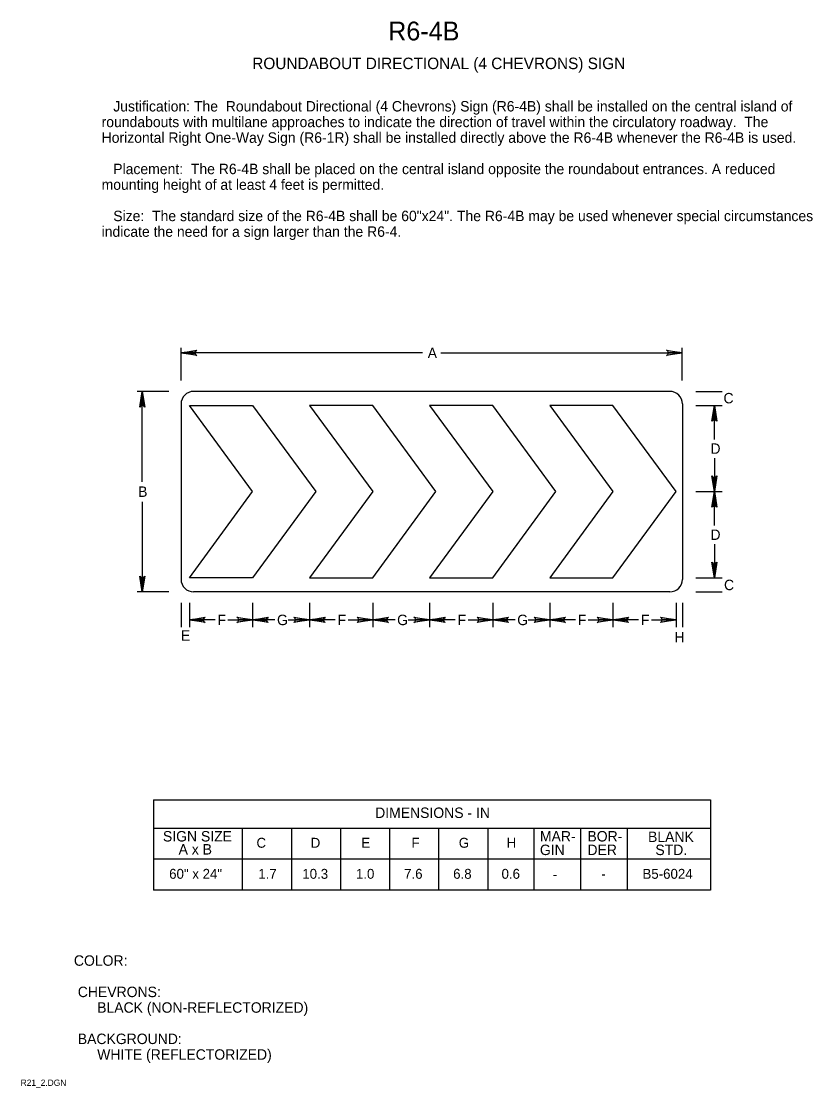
# Model space of a CAD drawing. Extents: x 0.013 to 0.202, y 0.004 to 0.259.
import ezdxf

# ---------------------------------------------------------------- set-up
doc = ezdxf.new("R2010")
doc.units = 0
for name, color, linetype in [('1', 7, 'Continuous'), ('2', 7, 'Continuous'), ('3', 7, 'Continuous')]:
    doc.layers.add(name, color=color, linetype=linetype)

# ---------------------------------------------------------------- blocks, each defined once
blk = doc.blocks.new('RARROW')
at = {"layer": '3'}
for p, q in [((-2.156, 0.285), (-2.2665, 0.384625)), ((-2.2665, 0.384625), (0, 0)), ((0, 0), (-2.2665, -0.379125)), ((-2.156, 0.285), (-2.075625, 0.12075)), ((0, 0), (-2.156, 0.285)), ((-2.14975, -0.2705), (0, 0)), ((-2.075625, 0.12075), (0, 0)), ((0, 0), (-2.074, -0.108)), ((-2.2665, -0.379125), (-2.14975, -0.2705)), ((-2.074, -0.108), (-2.14975, -0.2705))]:
    blk.add_line(p, q, dxfattribs=at)

msp = doc.modelspace()

# ---------------------------------------------------------------- linework, layer by layer
at = {"layer": '3'}
for p, q in [((0.05078, 0.1732), (0.05078, 0.18107)), ((0.10858, 0.17982), (0.05078, 0.17982)), ((0.11294, 0.17982), (0.17077, 0.17982)), ((0.17077, 0.1732), (0.17077, 0.18107)), ((0.04787, 0.17061), (0.04025, 0.17061)), ((0.0415, 0.14899), (0.0415, 0.17061)), ((0.16778, 0.17061), (0.05378, 0.17061)), ((0.17403, 0.17061), (0.18028, 0.17061)), ((0.05078, 0.16761), (0.05078, 0.12561)), ((0.0679, 0.14661), (0.05278, 0.16723)), ((0.05278, 0.16723), (0.0679, 0.16723)), ((0.17078, 0.16761), (0.17078, 0.12561)), ((0.17403, 0.16723), (0.18028, 0.16723)), ((0.17844, 0.15913), (0.17844, 0.16723)), ((0.17844, 0.15463), (0.17844, 0.14661)), ((0.05278, 0.12599), (0.0679, 0.14661)), ((0.17403, 0.14661), (0.18028, 0.14661)), ((0.17844, 0.1385), (0.17844, 0.14661)), ((0.0415, 0.1442), (0.0415, 0.12261)), ((0.17844, 0.13401), (0.17844, 0.12599)), ((0.17403, 0.12599), (0.18028, 0.12599)), ((0.04787, 0.12261), (0.04025, 0.12261)), ((0.16778, 0.12261), (0.05378, 0.12261)), ((0.17403, 0.12261), (0.18028, 0.12261)), ((0.05078, 0.12001), (0.05078, 0.11419)), ((0.05278, 0.12001), (0.05278, 0.11419)), ((0.0679, 0.12001), (0.0679, 0.11419)), ((0.08153, 0.12001), (0.08153, 0.11419)), ((0.09665, 0.12001), (0.09665, 0.11419)), ((0.11028, 0.12001), (0.11028, 0.11419)), ((0.1254, 0.12001), (0.1254, 0.11419)), ((0.13903, 0.12001), (0.13903, 0.11419)), ((0.15415, 0.12001), (0.15415, 0.11419)), ((0.16928, 0.12001), (0.16928, 0.11419)), ((0.17078, 0.12001), (0.17078, 0.11419)), ((0.05893, 0.11591), (0.0529, 0.11591)), ((0.062, 0.11591), (0.0679, 0.11591)), ((0.07325, 0.11591), (0.0679, 0.11591)), ((0.07641, 0.11591), (0.08153, 0.11591)), ((0.08768, 0.11591), (0.08165, 0.11591)), ((0.09075, 0.11591), (0.09665, 0.11591)), ((0.102, 0.11591), (0.09665, 0.11591)), ((0.10516, 0.11591), (0.11028, 0.11591)), ((0.11643, 0.11591), (0.1104, 0.11591)), ((0.1195, 0.11591), (0.1254, 0.11591)), ((0.13075, 0.11591), (0.1254, 0.11591)), ((0.13391, 0.11591), (0.13903, 0.11591)), ((0.14518, 0.11591), (0.13915, 0.11591)), ((0.14825, 0.11591), (0.15415, 0.11591)), ((0.1603, 0.11591), (0.15428, 0.11591)), ((0.16337, 0.11591), (0.16928, 0.11591)), ((0.04419, 0.07287), (0.17756, 0.07287)), ((0.04419, 0.07287), (0.04419, 0.05125)), ((0.17756, 0.07287), (0.17756, 0.05125)), ((0.17756, 0.066), (0.04419, 0.066)), ((0.06544, 0.066), (0.06544, 0.05125)), ((0.07719, 0.066), (0.07719, 0.05125)), ((0.08894, 0.066), (0.08894, 0.05125)), ((0.10069, 0.066), (0.10069, 0.05125)), ((0.11244, 0.066), (0.11244, 0.05125)), ((0.12419, 0.066), (0.12419, 0.05125)), ((0.12419, 0.066), (0.12419, 0.05262)), ((0.1352, 0.066), (0.1352, 0.05125)), ((0.14644, 0.066), (0.14644, 0.05125)), ((0.15756, 0.066), (0.15756, 0.05125)), ((0.17756, 0.05862), (0.04419, 0.05862)), ((0.17756, 0.05125), (0.04419, 0.05125))]:
    msp.add_line(p, q, dxfattribs=at)
msp.add_lwpolyline([(0.0679, 0.16723), (0.08302, 0.14661), (0.0679, 0.12599), (0.05278, 0.12599)], dxfattribs=at)
for points in [[(0.09665, 0.16723), (0.08153, 0.16723), (0.09665, 0.14661), (0.08153, 0.12599), (0.09665, 0.12599), (0.11177, 0.14661)], [(0.1254, 0.16723), (0.11028, 0.16723), (0.1254, 0.14661), (0.11028, 0.12599), (0.1254, 0.12599), (0.14052, 0.14661)], [(0.15415, 0.16723), (0.13903, 0.16723), (0.15415, 0.14661), (0.13903, 0.12599), (0.15415, 0.12599), (0.16927, 0.14661)]]:
    msp.add_lwpolyline(points, close=True, dxfattribs=at)
for centre, start, end in [((0.05378, 0.16761), 90, 180), ((0.16778, 0.16761), 0, 90), ((0.05378, 0.12561), 180, 270), ((0.16778, 0.12561), 270, 0)]:
    msp.add_arc(centre, 0.003, start, end, dxfattribs=at)

# ---------------------------------------------------------------- block references
at = {"layer": '3', "xscale": 0.0016545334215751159, "yscale": 0.0016366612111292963}
for p, rotation in [((0.05078, 0.17982), 180), ((0.0415, 0.17061), 90), ((0.17844, 0.16723), 90), ((0.17844, 0.14661), -90), ((0.17844, 0.14661), 90), ((0.17844, 0.12599), -90), ((0.0415, 0.12261), -90), ((0.05278, 0.11591), 180), ((0.0679, 0.11591), 180), ((0.08153, 0.11591), 180), ((0.09665, 0.11591), 180), ((0.11028, 0.11591), 180), ((0.1254, 0.11591), 180), ((0.13903, 0.11591), 180), ((0.15415, 0.11591), 180)]:
    msp.add_blockref('RARROW', p, dxfattribs=dict(at, rotation=rotation))
for p in [(0.17077, 0.17982), (0.0679, 0.11591), (0.08153, 0.11591), (0.09665, 0.11591), (0.11028, 0.11591), (0.1254, 0.11591), (0.13903, 0.11591), (0.15415, 0.11591), (0.16928, 0.11591)]:
    msp.add_blockref('RARROW', p, dxfattribs=at)

# ---------------------------------------------------------------- texts
at = {"layer": '1'}
for s, height, p in [('R6-4B', 0.0045, (0.10036, 0.25462)), ('ROUNDABOUT DIRECTIONAL (4 CHEVRONS) SIGN', 0.0027503, (0.06782, 0.24775)), ('COLOR:', 0.0025, (0.02513, 0.03312)), (' CHEVRONS:', 0.0025, (0.02513, 0.02562)), ('      BLACK (NON-REFLECTORIZED)', 0.0024998, (0.02513, 0.02188)), (' BACKGROUND:', 0.0024998, (0.02513, 0.01438)), ('      WHITE (REFLECTORIZED)', 0.0024998, (0.02513, 0.01063)), ('R21_2.DGN', 0.0015, (0.01238, 0.00438))]:
    msp.add_text(s, height=height, dxfattribs=at).set_placement(p)
at = {"layer": '2'}
for s, height, p in [('   Justification: The  Roundabout Directional (4 Chevrons) Sign (R6-4B) shall be installed on the central island of', 0.00249975, (0.03176, 0.23761)), ('roundabouts with multilane approaches to indicate the direction of travel within the circulatory roadway.  The ', 0.00249975, (0.03176, 0.23386)), ('Horizontal Right One-Way Sign (R6-1R) shall be installed directly above the R6-4B whenever the R6-4B is used.', 0.00249975, (0.03176, 0.23011)), ('   Placement:  The R6-4B shall be placed on the central island opposite the roundabout entrances. A reduced', 0.00249975, (0.03176, 0.22261)), ('mounting height of at least 4 feet is permitted.', 0.0024998, (0.03176, 0.21886)), ('   Size:  The standard size of the R6-4B shall be 60"x24". The R6-4B may be used whenever special circumstances ', 0.00249975, (0.03176, 0.21136)), ('indicate the need for a sign larger than the R6-4.', 0.0024998, (0.03176, 0.20761))]:
    msp.add_text(s, height=height, dxfattribs=at).set_placement(p)
at = {"layer": '3'}
for s, height, p in [('A', 0.0025, (0.10982, 0.17857)), ('C', 0.0025, (0.18063, 0.16774)), ('D', 0.0025, (0.17751, 0.15567)), ('B', 0.0025, (0.0405, 0.14536)), ('D', 0.0025, (0.17751, 0.13505)), ('C', 0.0025, (0.18076, 0.12303)), ('F', 0.0025, (0.05949, 0.11466)), ('G', 0.0025, (0.07375, 0.11466)), ('F', 0.0025, (0.08824, 0.11466)), ('G', 0.0025, (0.1025, 0.11466)), ('F', 0.0025, (0.11699, 0.11466)), ('G', 0.0025, (0.13125, 0.11466)), ('F', 0.0025, (0.14574, 0.11466)), ('F', 0.0025, (0.16086, 0.11466)), ('E', 0.0025, (0.05076, 0.11092)), ('H', 0.0025, (0.16889, 0.11054)), ('DIMENSIONS - IN', 0.0024998, (0.09724, 0.0685)), ('SIGN SIZE', 0.0025, (0.04644, 0.06287)), ('MAR-', 0.0025, (0.13669, 0.06287)), ('BOR-', 0.0025, (0.14806, 0.06287)), ('BLANK', 0.0025, (0.16257, 0.06275)), ('A x B', 0.0025, (0.05019, 0.05975)), (' C', 0.002375, (0.06795, 0.06137)), ('D', 0.00238, (0.08181, 0.06137)), ('E', 0.00238, (0.09394, 0.06137)), ('F', 0.00238, (0.10594, 0.06137)), ('G', 0.00238, (0.11727, 0.06137)), ('H', 0.00238, (0.12872, 0.06137)), ('GIN', 0.0025, (0.13669, 0.05962)), ('DER', 0.0025, (0.14806, 0.05962)), ('STD.', 0.0025, (0.16432, 0.05962)), ('60" x 24"', 0.002375, (0.04793, 0.05394)), ('1.7', 0.002375, (0.06927, 0.05394)), ('10.3', 0.002375, (0.0798, 0.05394)), ('1.0', 0.002375, (0.09264, 0.05394)), ('7.6', 0.002375, (0.10418, 0.05394)), ('6.8', 0.002375, (0.11592, 0.05394)), ('0.6', 0.002375, (0.1275, 0.05394)), ('B5-6024', 0.002375, (0.16124, 0.05394)), ('-', 0.00238, (0.13979, 0.05381)), ('-', 0.00238, (0.15138, 0.05394))]:
    msp.add_text(s, height=height, dxfattribs=at).set_placement(p)

doc.saveas('drawing.dxf')
